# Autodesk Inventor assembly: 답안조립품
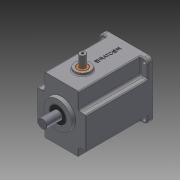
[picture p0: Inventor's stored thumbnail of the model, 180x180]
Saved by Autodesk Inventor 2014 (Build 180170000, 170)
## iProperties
Created: 2016-02
Part Number: 답안조립품
Document SubType Name: Assembly
Designer: Owner
Author: Owner
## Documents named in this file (13)
- C:\Documents and Settings\Owner\바탕 화면\360211V1004\답안조립품.iam
- C:\Documents and Settings\Owner\바탕 화면\360211V1004\본체.ipt
- C:\Documents and Settings\Owner\바탕 화면\360211V1004\커버.ipt
- C:\Documents and Settings\Owner\바탕 화면\360211V1004\오일실 8 22 7.ipt
- C:\Documents and Settings\Owner\바탕 화면\360211V1004\볼트 M4 x 10.ipt
- C:\Documents and Settings\Owner\바탕 화면\360211V1004\베어링 608.ipt
- C:\Documents and Settings\Owner\바탕 화면\360211V1004\메인축.ipt
- C:\Documents and Settings\Owner\바탕 화면\360211V1004\서브축.ipt
- C:\Documents and Settings\Owner\바탕 화면\360211V1004\베어링 6003.ipt
- C:\Documents and Settings\Owner\바탕 화면\360211V1004\오일실 17 32 8.ipt
- C:\Documents and Settings\Owner\바탕 화면\360211V1004\부시.ipt
- C:\Documents and Settings\Owner\바탕 화면\360211V1004\슬라이더.ipt
- C:\Documents and Settings\Owner\바탕 화면\360211V1004\12. 가변스프링1.ipt
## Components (3 placed, 2 different names)
1. 12. 가변스프링1:1
2. ISO 4762 M4 x 10:1
3. ISO 4762 M4 x 10:2
